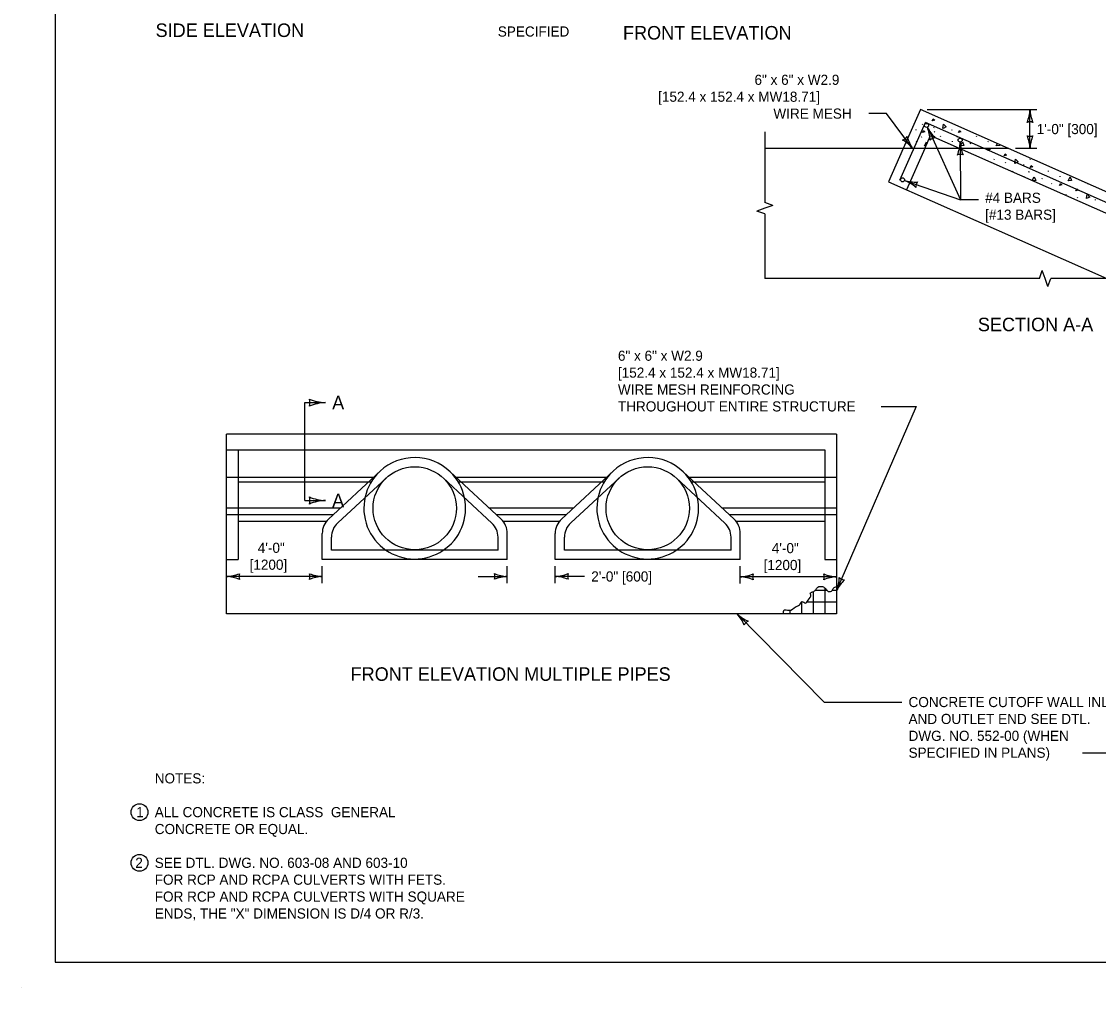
# Model space of a CAD drawing. Extents: x 49991.4 to 50021, y 49987.6 to 50011.4.
# Drawn here: x 50009.54 to 50015.92, y 49999.74 to 50005.45 of the extents above; entities that cross this region are included whole.
import ezdxf

# ---------------------------------------------------------------- set-up
doc = ezdxf.new("R2010")
doc.units = 0
for name, color, linetype in [('Level 1', 7, 'Continuous'), ('Level 2', 7, 'Continuous'), ('Level 3', 7, 'Continuous'), ('Level 4', 7, 'Continuous'), ('Level 6', 7, 'Continuous')]:
    doc.layers.add(name, color=color, linetype=linetype)

msp = doc.modelspace()

# ---------------------------------------------------------------- linework, layer by layer
at = {"layer": 'Level 1'}
for p, q in [((50014.8623, 50004.9337), (50014.7599, 50004.7021)), ((50017.1247, 50003.9332), (50014.8623, 50004.9337)), ((50014.7411, 50004.5151), (50014.8922, 50004.8567)), ((50014.8372, 50004.8711), (50014.8381, 50004.8721)), ((50016.9755, 50003.9332), (50014.8922, 50004.8567)), ((50014.8349, 50004.8148), (50014.8354, 50004.8108)), ((50014.8746, 50004.8441), (50014.8763, 50004.8481)), ((50014.942, 50004.8259), (50014.9438, 50004.8299)), ((50014.948, 50004.8003), (50014.9446, 50004.803)), ((50015.0476, 50004.8148), (50015.0481, 50004.8108)), ((50014.839, 50004.7415), (50014.8408, 50004.7455)), ((50014.867, 50004.7734), (50014.8688, 50004.7707)), ((50014.8878, 50004.7021), (50014.922, 50004.7792)), ((50014.922, 50004.7792), (50016.8348, 50003.9332)), ((50014.9824, 50004.7744), (50014.9842, 50004.7784)), ((50015.0517, 50004.7415), (50015.0535, 50004.7455)), ((50015.0779, 50004.7744), (50015.0797, 50004.7718)), ((50015.0797, 50004.7734), (50015.0815, 50004.7707)), ((50015.1536, 50004.7409), (50015.1502, 50004.7437)), ((50015.1592, 50004.7313), (50015.1609, 50004.7353)), ((50015.1951, 50004.7744), (50015.1969, 50004.7784)), ((50015.2644, 50004.7415), (50015.2662, 50004.7455)), ((50015.386, 50004.7021), (50013.9406, 50004.7021)), ((50014.7893, 50004.7029), (50014.7898, 50004.7021)), ((50014.8239, 50004.7145), (50014.8241, 50004.7137)), ((50015.2147, 50004.7029), (50015.2164, 50004.7002)), ((50015.246, 50004.7025), (50015.2457, 50004.7013)), ((50015.2999, 50004.6367), (50015.3017, 50004.6407)), ((50015.3674, 50004.6185), (50015.3692, 50004.6225)), ((50015.473, 50004.6074), (50015.4734, 50004.6034)), ((50015.5126, 50004.6367), (50015.5144, 50004.6407)), ((50015.4078, 50004.567), (50015.4096, 50004.571)), ((50015.4771, 50004.5341), (50015.4789, 50004.5381)), ((50015.5033, 50004.567), (50015.5051, 50004.5643)), ((50015.5051, 50004.566), (50015.5068, 50004.5633)), ((50015.6205, 50004.567), (50015.6223, 50004.571)), ((50015.6898, 50004.5341), (50015.6915, 50004.5381)), ((50015.5845, 50004.5239), (50015.5863, 50004.5279)), ((50015.64, 50004.4955), (50015.6418, 50004.4928)), ((50015.8527, 50004.4955), (50015.8545, 50004.4928)), ((50015.7253, 50004.4293), (50015.7271, 50004.4333)), ((50015.7928, 50004.4111), (50015.7946, 50004.4151)), ((50015.8984, 50004.4), (50015.8988, 50004.396)), ((50010.7517, 50001.9468), (50010.7517, 50003.0108)), ((50014.366, 50003.0108), (50010.7517, 50003.0108)), ((50014.366, 50003.0108), (50014.366, 50001.9468)), ((50011.6612, 50002.7922), (50011.3554, 50002.508)), ((50011.6991, 50002.7527), (50011.4104, 50002.486)), ((50012.0349, 50002.7526), (50012.3235, 50002.4854)), ((50012.0763, 50002.7888), (50012.3783, 50002.508)), ((50013.0415, 50002.7922), (50012.7357, 50002.508)), ((50013.0794, 50002.7527), (50012.7907, 50002.486)), ((50013.4152, 50002.7526), (50013.7038, 50002.4854)), ((50013.4566, 50002.7888), (50013.7586, 50002.508)), ((50010.7517, 50002.5745), (50011.427, 50002.5745)), ((50012.3067, 50002.5745), (50012.8073, 50002.5745)), ((50013.687, 50002.5745), (50014.366, 50002.5745)), ((50010.7517, 50002.5349), (50011.3844, 50002.5349)), ((50012.3493, 50002.5349), (50012.7647, 50002.5349)), ((50013.7296, 50002.5349), (50014.366, 50002.5349)), ((50011.3187, 50002.2691), (50011.3188, 50002.4241)), ((50012.415, 50002.2691), (50012.4151, 50002.4239)), ((50012.699, 50002.2691), (50012.6991, 50002.4241)), ((50013.7953, 50002.2691), (50013.7954, 50002.4239)), ((50011.3736, 50002.3238), (50011.3736, 50002.4019)), ((50012.3602, 50002.3238), (50012.3603, 50002.4014)), ((50012.7539, 50002.3238), (50012.7539, 50002.4019)), ((50013.7405, 50002.3238), (50013.7406, 50002.4014)), ((50012.3602, 50002.3238), (50011.3736, 50002.3238)), ((50013.7405, 50002.3238), (50012.7539, 50002.3238)), ((50012.415, 50002.2691), (50011.3187, 50002.2691)), ((50013.7953, 50002.2691), (50012.699, 50002.2691)), ((50014.2272, 50002.0783), (50014.2272, 50001.9468)), ((50014.3111, 50002.0857), (50014.2362, 50002.0857)), ((50014.2965, 50002.1003), (50014.2965, 50001.9468)), ((50014.366, 50002.0857), (50014.339, 50002.0857)), ((50014.1577, 50002.018), (50014.1577, 50001.9468)), ((50014.366, 50002.0162), (50014.1872, 50002.0162)), ((50014.366, 50001.9468), (50010.7517, 50001.9468)), ((50014.0884, 50001.9714), (50014.0884, 50001.9468)), ((50009.5374, 49999.7356), (50009.5374, 49999.7356))]:
    msp.add_line(p, q, dxfattribs=at)
msp.add_lwpolyline([(50020.9378, 50008.1646), (50009.7374, 50008.1646), (50009.7374, 49999.8856), (50020.9378, 49999.8856)], close=True, dxfattribs=at)
for points in [[(50014.8491, 50004.9039), (50014.8501, 50004.9032), (50014.8486, 50004.9027)], [(50014.9332, 50004.867), (50014.9386, 50004.8781), (50014.9475, 50004.8714), (50014.9332, 50004.867)], [(50014.8754, 50004.7975), (50014.8808, 50004.8086), (50014.8896, 50004.8019), (50014.8754, 50004.7975)], [(50014.9961, 50004.8213), (50014.9996, 50004.8467), (50015.0155, 50004.8303), (50014.9965, 50004.8215)], [(50015.0881, 50004.7975), (50015.0935, 50004.8086), (50015.1023, 50004.8019), (50015.0881, 50004.7975)], [(50014.8865, 50004.7193), (50014.8985, 50004.742), (50014.902, 50004.7342)], [(50015.0992, 50004.7193), (50015.1112, 50004.742), (50015.1205, 50004.7211), (50015.0997, 50004.7193)], [(50015.3119, 50004.7193), (50015.3186, 50004.7319)], [(50015.3308, 50004.7265), (50015.3332, 50004.7211), (50015.3124, 50004.7193)], [(50014.8411, 50004.7021), (50014.8412, 50004.7024), (50014.8416, 50004.7021)], [(50014.8958, 50004.7201), (50014.887, 50004.7193)], [(50015.2613, 50004.6913), (50015.2666, 50004.7024), (50015.2755, 50004.6958), (50015.2613, 50004.6913)], [(50015.3586, 50004.6596), (50015.364, 50004.6707), (50015.3728, 50004.664), (50015.3586, 50004.6596)], [(50015.4214, 50004.6139), (50015.425, 50004.6393), (50015.4409, 50004.6229), (50015.4219, 50004.6141)], [(50015.5135, 50004.5901), (50015.5188, 50004.6012), (50015.5277, 50004.5945), (50015.5135, 50004.5901)], [(50015.5249, 50004.5125), (50015.5366, 50004.5345), (50015.5459, 50004.5137), (50015.5261, 50004.512)], [(50015.7373, 50004.5119), (50015.7493, 50004.5345), (50015.7586, 50004.5137), (50015.7377, 50004.5119)], [(50015.6867, 50004.4839), (50015.692, 50004.495), (50015.7009, 50004.4884), (50015.6867, 50004.4839)], [(50015.784, 50004.4522), (50015.7893, 50004.4633), (50015.7982, 50004.4566), (50015.784, 50004.4522)], [(50015.8468, 50004.4065), (50015.8503, 50004.4319), (50015.8662, 50004.4155), (50015.8472, 50004.4067)]]:
    msp.add_lwpolyline(points, dxfattribs=at)
for centre in [(50014.8988, 50004.8394), (50015.098, 50004.7524), (50014.7567, 50004.5171)]:
    msp.add_circle(centre, 0.012, dxfattribs=at)
for centre, major_axis, start_param, end_param in [((50011.8669, 50002.5726), (0.3015, 0), 0.803192, 2.321661), ((50013.2472, 50002.5726), (0.3015, 0), 0.803192, 2.321661), ((50011.4339, 50002.4241), (-0.1151, 0), 5.463072, 6.283185), ((50012.3, 50002.4239), (0.1151, 0), 0, 0.82267), ((50012.8142, 50002.4241), (-0.1151, 0), 5.463072, 6.283185), ((50013.6803, 50002.4239), (0.1151, 0), 0, 0.82267), ((50011.4887, 50002.4019), (-0.1151, 0), 5.460236, 6.283185), ((50012.2452, 50002.4014), (0.1151, 0), 0, 0.822133), ((50012.869, 50002.4019), (-0.1151, 0), 5.460236, 6.283185), ((50013.6255, 50002.4014), (0.1151, 0), 0, 0.822133)]:
    msp.add_ellipse(centre, major_axis=major_axis, ratio=0.996203, start_param=start_param, end_param=end_param, dxfattribs=at)
for centre in [(50011.8669, 50002.5726), (50013.2472, 50002.5726)]:
    msp.add_ellipse(centre, major_axis=(0.2467, 0), ratio=0.996203, dxfattribs=at)
msp.add_spline([(50014.051, 50001.9468), (50014.0561, 50001.9704), (50014.0819, 50001.9684), (50014.1264, 50001.9906), (50014.1499, 50002.0053), (50014.1548, 50002.0152), (50014.161, 50002.0201), (50014.182, 50002.0115), (50014.1968, 50002.0287), (50014.2129, 50002.0595), (50014.2104, 50002.0681), (50014.2302, 50002.0804), (50014.245, 50002.0939), (50014.2549, 50002.1062), (50014.2821, 50002.1087), (50014.3018, 50002.0964), (50014.3166, 50002.0804), (50014.3401, 50002.0866), (50014.3488, 50002.1013), (50014.366, 50002.1096)], degree=3, dxfattribs=at)
at = {"layer": 'Level 2'}
for centre in [(50010.2365, 50000.7736), (50010.2365, 50000.4736)]:
    msp.add_circle(centre, 0.05, dxfattribs=at)
at = {"layer": 'Level 3'}
for p, q in [((50014.9023, 50004.9337), (50015.5517, 50004.9337)), ((50015.5117, 50004.7021), (50015.5117, 50004.9337)), ((50014.6607, 50004.9094), (50014.5564, 50004.9094)), ((50014.8165, 50004.7021), (50014.6607, 50004.9094)), ((50014.9038, 50004.8285), (50015.1008, 50004.399)), ((50015.0981, 50004.7404), (50015.1008, 50004.399)), ((50015.5517, 50004.7021), (50015.426, 50004.7021)), ((50014.768, 50004.5132), (50015.1008, 50004.399)), ((50015.2065, 50004.399), (50015.1008, 50004.399)), ((50014.8375, 50003.1758), (50014.366, 50002.0857)), ((50014.6296, 50003.1758), (50014.8375, 50003.1758)), ((50011.3192, 50002.1686), (50010.7517, 50002.1686)), ((50011.3192, 50002.1286), (50011.3192, 50002.2291)), ((50012.2416, 50002.1689), (50012.415, 50002.1689)), ((50012.415, 50002.1289), (50012.415, 50002.2291)), ((50012.699, 50002.1289), (50012.699, 50002.2291)), ((50012.8724, 50002.1689), (50012.699, 50002.1689)), ((50013.7953, 50002.1267), (50013.7953, 50002.2291)), ((50014.366, 50002.1667), (50013.7953, 50002.1667)), ((50013.7772, 50001.9468), (50014.2918, 50001.4254)), ((50014.2918, 50001.4254), (50014.7523, 50001.4254)), ((50015.8224, 50001.1251), (50016.4513, 50001.1251))]:
    msp.add_line(p, q, dxfattribs=at)
for centre, radius, start, end in [((50015.2896, 50004.9429), 0.2223, 337.45601, 357.63952), ((50015.2896, 50004.9425), 0.2223, 337.45601, 357.63952), ((50015.7444, 50004.9452), 0.233, 182.82731, 202.07716), ((50015.7444, 50004.9448), 0.233, 182.82731, 202.07716), ((50015.5117, 50004.8055), 0.0548, 72.13882, 107.86118), ((50015.5117, 50004.8051), 0.0548, 72.13882, 107.86118), ((50014.6981, 50004.7442), 0.2223, 2.09565, 22.27916), ((50015.1105, 50004.9359), 0.233, 207.46695, 226.7168), ((50014.7395, 50004.8046), 0.0548, 289.06996, 324.79232), ((50014.6374, 50004.5531), 0.233, 39.75845, 59.0083), ((50014.9996, 50004.8283), 0.2223, 194.38715, 214.57066), ((50014.9573, 50004.7119), 0.0548, 96.77846, 132.50082), ((50014.8759, 50004.7478), 0.2223, 337.90913, 358.09264), ((50015.3307, 50004.7537), 0.233, 183.28043, 202.53028), ((50015.5117, 50004.8303), 0.0548, 252.13882, 287.86118), ((50015.279, 50004.6906), 0.233, 2.82731, 22.07716), ((50015.5117, 50004.8303), 0.0548, 252.13882, 287.86118), ((50015.279, 50004.6906), 0.233, 2.82731, 22.07716), ((50015.7338, 50004.6929), 0.2223, 157.45601, 177.63952), ((50015.7338, 50004.6929), 0.2223, 157.45601, 177.63952), ((50015.0991, 50004.6122), 0.0548, 72.59194, 108.3143), ((50014.6873, 50004.3061), 0.2223, 48.5164, 68.69991), ((50014.8327, 50004.737), 0.233, 253.8877, 273.13755), ((50014.8893, 50004.4716), 0.0548, 143.19921, 178.92157), ((50011.349, 50003.4762), 0.2779, 247.45601, 267.63952), ((50011.1773, 50003.1985), 0.0685, 342.13882, 17.86118), ((50011.352, 50002.9076), 0.2912, 92.82731, 112.07716), ((50011.349, 50002.8964), 0.2779, 247.45601, 267.63952), ((50011.1773, 50002.6187), 0.0685, 342.13882, 17.86118), ((50011.352, 50002.3278), 0.2912, 92.82731, 112.07716), ((50010.7402, 50002.4013), 0.233, 272.82731, 292.07716), ((50010.7425, 50001.9465), 0.2223, 67.45601, 87.63952), ((50010.8799, 50002.1686), 0.0548, 162.13882, 197.86118), ((50011.3284, 50002.3907), 0.2223, 247.45601, 267.63952), ((50011.191, 50002.1686), 0.0548, 342.13882, 17.86118), ((50011.3307, 50001.9359), 0.233, 92.82731, 112.07716), ((50012.4242, 50002.391), 0.2223, 247.45601, 267.63952), ((50012.2868, 50002.1689), 0.0548, 342.13882, 17.86118), ((50012.4265, 50001.9362), 0.233, 92.82731, 112.07716), ((50012.6875, 50002.4016), 0.233, 272.82731, 292.07716), ((50012.6898, 50001.9468), 0.2223, 67.45601, 87.63952), ((50012.8272, 50002.1689), 0.0548, 162.13882, 197.86118), ((50013.7838, 50002.3994), 0.233, 272.82731, 292.07716), ((50013.9235, 50002.1667), 0.0548, 162.13882, 197.86118), ((50014.3752, 50002.3888), 0.2223, 247.45601, 267.63952), ((50014.2378, 50002.1667), 0.0548, 342.13882, 17.86118), ((50013.7861, 50001.9446), 0.2223, 67.45601, 87.63952), ((50014.3775, 50001.934), 0.233, 92.82731, 112.07716), ((50014.1492, 50002.171), 0.233, 338.53362, 357.78347), ((50014.5647, 50001.986), 0.2223, 133.16232, 153.34583), ((50014.4187, 50002.2026), 0.0548, 227.84513, 263.56749), ((50013.6124, 50001.7976), 0.2223, 21.97362, 42.15713), ((50013.9351, 50002.1182), 0.233, 227.34492, 246.59477), ((50013.8671, 50001.8554), 0.0548, 116.65643, 152.37879)]:
    msp.add_arc(centre, radius, start, end, dxfattribs=at)
at = {"layer": 'Level 4'}
for p, q in [((50014.7599, 50004.7021), (50014.6729, 50004.5053)), ((50014.8878, 50004.7021), (50014.7797, 50004.4581)), ((50014.6729, 50004.5053), (50015.9669, 50003.9332)), ((50010.7517, 50002.9181), (50014.2965, 50002.9183)), ((50010.821, 50002.9181), (50010.821, 50002.2699)), ((50014.2965, 50002.9183), (50014.2965, 50002.2699)), ((50010.7517, 50002.757), (50011.6289, 50002.757)), ((50012.1049, 50002.757), (50013.0092, 50002.757)), ((50013.4852, 50002.757), (50014.366, 50002.757)), ((50010.821, 50002.7289), (50011.6095, 50002.7289)), ((50012.1244, 50002.7289), (50012.9898, 50002.7289)), ((50013.5047, 50002.7289), (50014.2965, 50002.7289)), ((50010.821, 50002.4964), (50011.3445, 50002.4964)), ((50012.3892, 50002.4964), (50012.7248, 50002.4964)), ((50013.7695, 50002.4964), (50014.2965, 50002.4964)), ((50010.7517, 50002.2699), (50010.821, 50002.2699)), ((50014.2965, 50002.2699), (50014.366, 50002.2699))]:
    msp.add_line(p, q, dxfattribs=at)
for centre in [(50011.8669, 50002.5726), (50013.2472, 50002.5726)]:
    msp.add_ellipse(centre, major_axis=(0.3015, 0), ratio=0.996203, start_param=2.321661, end_param=7.086377, dxfattribs=at)
at = {"layer": 'Level 6'}
for p, q in [((50013.9406, 50004.8021), (50013.9406, 50004.3826)), ((50013.9406, 50004.3492), (50013.8935, 50004.3325)), ((50013.9877, 50004.3659), (50013.9406, 50004.3826)), ((50013.9877, 50004.3659), (50013.9406, 50004.3492)), ((50013.9406, 50004.3158), (50013.8935, 50004.3325)), ((50013.9406, 50004.3158), (50013.9406, 50003.9332)), ((50015.5676, 50003.9332), (50015.5843, 50003.9803)), ((50015.601, 50003.9332), (50015.5843, 50003.9803)), ((50015.5676, 50003.9332), (50013.9406, 50003.9332)), ((50015.6177, 50003.8861), (50015.601, 50003.9332)), ((50015.6177, 50003.8861), (50015.6344, 50003.9332)), ((50017.2247, 50003.9332), (50015.6344, 50003.9332)), ((50011.2151, 50002.6187), (50011.2151, 50003.1985)), ((50011.2151, 50003.1985), (50011.3376, 50003.1985)), ((50011.2151, 50002.6187), (50011.3376, 50002.6187))]:
    msp.add_line(p, q, dxfattribs=at)

# ---------------------------------------------------------------- texts
at = {"layer": 'Level 2'}
for s, height, p in [('SIDE ELEVATION', 0.08, (50010.3316, 50005.3629)), ('SPECIFIED', 0.06, (50012.3589, 50005.3654)), ('FRONT ELEVATION', 0.08, (50013.1007, 50005.3479)), ('6" x 6" x W2.9', 0.06, (50013.8797, 50005.0794)), ('[152.4 x 152.4 x MW18.71]', 0.06, (50013.3088, 50004.9794)), ('WIRE MESH', 0.06, (50013.9917, 50004.8794)), ('1\'-0" [300]', 0.06, (50015.5517, 50004.7879)), ('#4 BARS', 0.06, (50015.246, 50004.3809)), ('[#13 BARS]', 0.06, (50015.246, 50004.2809)), ('SECTION A-A', 0.08, (50015.2029, 50003.6209)), ('6" x 6" x W2.9 ', 0.06, (50013.0706, 50003.4458)), ('[152.4 x 152.4 x MW18.71]', 0.06, (50013.0706, 50003.3458)), ('WIRE MESH REINFORCING ', 0.06, (50013.0706, 50003.2458)), ('A', 0.08, (50011.3776, 50003.1585)), ('THROUGHOUT ENTIRE STRUCTURE', 0.06, (50013.0706, 50003.1458)), ('A', 0.08, (50011.3776, 50002.5787)), ('4\'-0"', 0.06, (50010.937, 50002.3086)), ('4\'-0"', 0.06, (50013.9822, 50002.3067)), ('[1200]', 0.06, (50010.8883, 50002.2086)), ('[1200]', 0.06, (50013.9335, 50002.2067)), ('2\'-0" [600]', 0.06, (50012.9124, 50002.1389)), ('FRONT ELEVATION MULTIPLE PIPES', 0.08, (50011.4869, 50001.551)), ('CONCRETE CUTOFF WALL INLET', 0.06, (50014.7923, 50001.3954)), ('AND OUTLET END SEE DTL. ', 0.06, (50014.7923, 50001.2954)), ('DWG. NO. 552-00 (WHEN', 0.06, (50014.7923, 50001.1954)), ('SPECIFIED IN PLANS)', 0.06, (50014.7923, 50001.0954)), ('NOTES:', 0.06, (50010.3265, 50000.9436)), ('1', 0.06, (50010.2167, 50000.7436)), ('ALL CONCRETE IS CLASS  GENERAL', 0.06, (50010.3265, 50000.7436)), ('CONCRETE OR EQUAL.', 0.06, (50010.3265, 50000.6436)), ('2', 0.06, (50010.2113, 50000.4436)), ('SEE DTL. DWG. NO. 603-08 AND 603-10', 0.06, (50010.3265, 50000.4436)), ('FOR RCP AND RCPA CULVERTS WITH FETS.', 0.06, (50010.3265, 50000.3436)), ('FOR RCP AND RCPA CULVERTS WITH SQUARE', 0.06, (50010.3265, 50000.2436)), ('ENDS, THE "X" DIMENSION IS D/4 OR R/3.', 0.06, (50010.3265, 50000.1436))]:
    msp.add_text(s, height=height, dxfattribs=at).set_placement(p)

doc.saveas('drawing.dxf')
